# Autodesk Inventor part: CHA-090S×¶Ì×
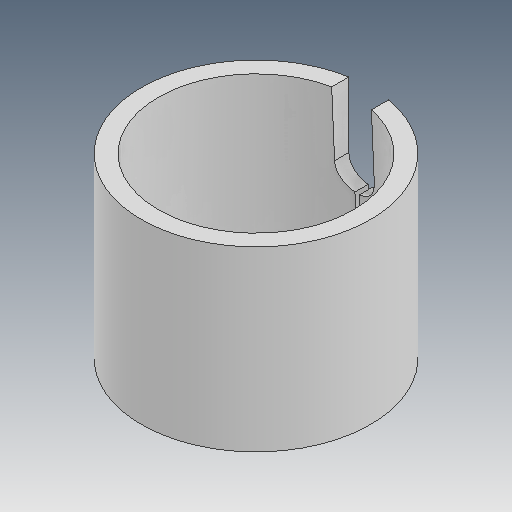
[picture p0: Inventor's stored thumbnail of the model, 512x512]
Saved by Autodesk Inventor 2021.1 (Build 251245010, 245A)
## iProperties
Created: 2019-05
Part Number: CHA-090S×¶Ì×
Material: Ogólny
Document SubType Name: Modeling
Designer: user
Density: 1 g/cm^3
Appearance: Domyślna
Author: user
Revision Number: ÈÎºÎ
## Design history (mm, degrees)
feature "ÊäÈë1"
node "Bryła1"
